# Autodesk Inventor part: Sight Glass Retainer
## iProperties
Created: 2007-11
Part Number: Sight Glass Retainer
Document SubType Name: Modeling
Designer: CM
Density: 1 g/cm^3
Mass: 7.18755 g
Surface Area: 51.5185 cm^2
Volume: 7.18755 cm^3
Author: CM
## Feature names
1. Extrusion1
2. Hole1
3. Circular Pattern1
4. Revolution1
5. Revolution2
